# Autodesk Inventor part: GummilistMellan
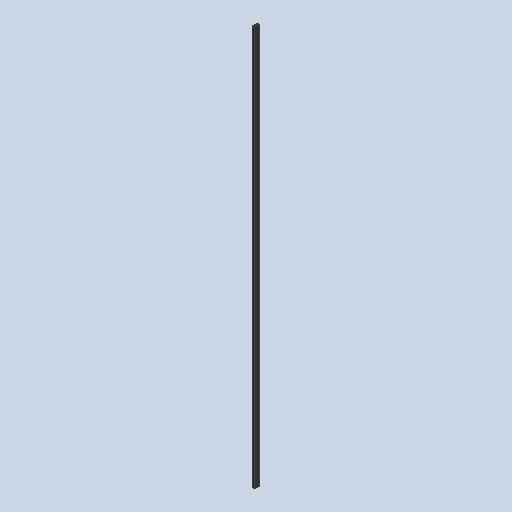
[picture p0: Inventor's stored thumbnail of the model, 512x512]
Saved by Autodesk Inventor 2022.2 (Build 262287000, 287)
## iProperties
Created: 2019-06
Part Number: GummilistMellan
Material: Rubber
Document SubType Name: Modeling
Designer: cl
Density: 0.93 g/cm^3
Appearance: Rubber - Black
Author: cl
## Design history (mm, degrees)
sketch "Sketch1"
  geometry: L1 (0, 0)-(20, 0); L2 (25, -5)-(25, -45); L3 (20, -50)-(0, -50); L4 (0, -50)-(0, 0); A1 r 5 centre (20, -5) between (25, -5) and (20, 0); A2 r 5 centre (20, -45) between (20, -50) and (25, -45); 2 further points
  constraints: 8 end point, 4 point on circle, 4 point on line, 4 tangent, 2 centre point, 2 parallel, 1 equal radius, 1 horizontal, 1 perpendicular
  dimensions: "d0" = 25 distance of point (25, -50) L3.end; "d1" = 50 distance of point (25, 0) point (25, -50); "d2" = 5 radius of A1
extrude "Extrusion1" new body sketch "Sketch1" distance "d3" = 3991 (computed from Daghöjd_1); taper "d4" = 0 deg
body "Solid1"
other parameters: "BladBredd" = 987.5, "Fönsterhöjd" = 862
